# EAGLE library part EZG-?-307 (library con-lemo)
LEMO Connector Source: http://www.lemo.com/pdfs/catalog/ROW/German/unipole_multipole.pdf
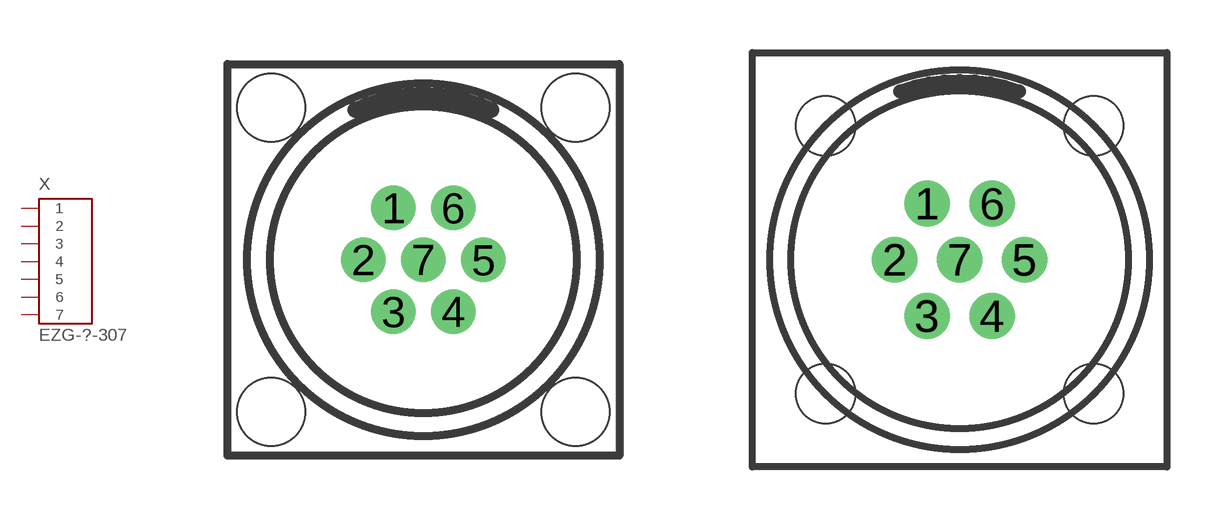
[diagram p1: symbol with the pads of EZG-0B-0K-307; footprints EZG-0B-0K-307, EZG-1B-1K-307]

Designator prefix X

## EZG-0B-307 (OC_FARNELL: unknown; OC_NEWARK: unknown)  [EZG-0B-0K-307]
1  1  pas
2  2  pas
3  3  pas
4  4  pas
5  5  pas
6  6  pas
7  7  pas

## EZG-0K-307 (OC_FARNELL: unknown; OC_NEWARK: unknown)  [EZG-0B-0K-307]
Pads as for EZG-0B-0K-307

## EZG-1B-307 (OC_FARNELL: unknown; OC_NEWARK: unknown)  [EZG-1B-1K-307]
Pads as for EZG-0B-0K-307

## EZG-1K-307 (OC_FARNELL: unknown; OC_NEWARK: unknown)  [EZG-1B-1K-307]
Pads as for EZG-0B-0K-307

## EZG-2B-307 (OC_FARNELL: unknown; OC_NEWARK: unknown)  [EZG-2B-2K-307]
Pads as for EZG-0B-0K-307

## EZG-2K-307 (OC_FARNELL: unknown; OC_NEWARK: unknown)  [EZG-2B-2K-307]
Pads as for EZG-0B-0K-307

## Footprint EZG-0B-0K-307 (pad centres in mm)
LEMO Connector Source: http://www.lemo.com/pdfs/catalog/ROW/German/unipole_multipole.pdf
drill 0.6 pad 1.1 round: 1 -0.75,1.299; 2 -1.5,0; 3 -0.75,-1.299; 4 0.75,-1.299; 5 1.5,0; 6 0.75,1.299; 7 0,0
hole 1.7 at -3.81,3.81
hole 1.7 at 3.81,3.81
hole 1.7 at 3.81,-3.81
hole 1.7 at -3.81,-3.81

## Footprint EZG-1B-1K-307 (pad centres in mm)
LEMO Connector Source: http://www.lemo.com/pdfs/catalog/ROW/German/unipole_multipole.pdf
drill 0.8 pad 1.3 round: 1 -0.925,1.602; 2 -1.85,0; 3 -0.925,-1.602; 4 0.925,-1.602; 5 1.85,0; 6 0.925,1.602; 7 0,0
hole 1.7 at -3.81,3.81
hole 1.7 at 3.81,3.81
hole 1.7 at 3.81,-3.81
hole 1.7 at -3.81,-3.81

## Footprint EZG-2B-2K-307 (pad centres in mm)
LEMO Connector Source: http://www.lemo.com/pdfs/catalog/ROW/German/unipole_multipole.pdf
drill 0.8 pad 1.3 round: 1 -1.45,2.511; 2 -2.9,0; 3 -1.45,-2.511; 4 1.45,-2.511; 5 2.9,0; 6 1.45,2.511; 7 0,0
hole 1.7 at -5.08,5.08
hole 1.7 at 5.08,5.08
hole 1.7 at 5.08,-5.08
hole 1.7 at -5.08,-5.08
